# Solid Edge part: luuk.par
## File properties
Author: Mac
Template: Normal.par
Last saved by: Mac
Revision: 4
Application: Solid Edge
Density: 1300,000 kg/m^3
Accuracy: 0,990
Material: Epoxy, cast rigid
Face Style: White
Fill Style: ANSI34(Plastic)
Virtual Style: Shiny resin yellow
Coef. of Thermal Exp: 5.9e-05
Thermal Conductivity: 2.1
Specific Heat: 0.0
Modulus of Elasticity: 3102640650.0
Poission's Ratio: 0.37
Yield Stress: 65500191.5
Ultimate Stress: 0.0
Elongation: 0.0
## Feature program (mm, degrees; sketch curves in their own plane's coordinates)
sketch for "unnamed Protrusion 1" plane through (0, 0, 0) normal (0, 0, 1) x-axis (1, 0, 0)
  line (-16, 26) -> (0, 26)
  line (0, 26) -> (0, 0)
  line (0, 0) -> (-16, 0)
  line (-16, 0) -> (-16, 26)
extrude "unnamed Protrusion 1" add finite 0.5 along +normal
fillet "Round_1" radius 0.02
thinwall "Thinwall_2"  Thickness = 0.1 mm
sketch for "unnamed Cutout 1" plane through (-8, 13, 0.5) normal (0, 0, 1) x-axis (1, 0, 0)
  circle centre (-6.43, 0) radius 0.7
extrude "unnamed Cutout 1" cut through along -normal
sketch for "ExtrudedCutout_2" #1 plane through (-8, 13, 0.5) normal (0, 0, 1) x-axis (1, 0, 0)
  line (7.85, 9.4) -> (7.1461, 9.5241)
  arc centre (7.16, 9.6029) radius 0.08 from (7.08, 9.6029) to (7.1461, 9.5241) ccw
  line (7.08, 9.6029) -> (7.08, 10.3971)
  arc centre (7.16, 10.3971) radius 0.08 from (7.08, 10.3971) to (7.1461, 10.4759) cw
  line (7.85, 10.6) -> (7.1461, 10.4759)
  line (7.85, 10.6) -> (8.2871, 10.6)
  line (8.2871, 9.4) -> (8.2871, 10.6)
  line (7.85, 9.4) -> (8.2871, 9.4)
sketch for "ExtrudedCutout_2" #2 plane through (-8, 13, 0.5) normal (0, 0, 1) x-axis (1, 0, 0)
  line (7.85, -9.4) -> (7.1461, -9.5241)
  arc centre (7.16, -9.6029) radius 0.08 from (7.08, -9.6029) to (7.1461, -9.5241) cw
  line (7.08, -9.6029) -> (7.08, -10.3971)
  arc centre (7.16, -10.3971) radius 0.08 from (7.08, -10.3971) to (7.1461, -10.4759) ccw
  line (7.85, -10.6) -> (7.1461, -10.4759)
  line (7.85, -10.6) -> (8.2871, -10.6)
  line (8.2871, -9.4) -> (8.2871, -10.6)
  line (7.85, -9.4) -> (8.2871, -9.4)
sketch for "ExtrudedCutout_2" #3 plane through (-8, 13, 0.5) normal (0, 0, 1) x-axis (1, 0, 0)
  line (7.85, 0.6) -> (7.1461, 0.4759)
  arc centre (7.16, 0.3971) radius 0.08 from (7.08, 0.3971) to (7.1461, 0.4759) cw
  line (7.08, 0.3971) -> (7.08, -0.3971)
  arc centre (7.16, -0.3971) radius 0.08 from (7.08, -0.3971) to (7.1461, -0.4759) ccw
  line (7.85, -0.6) -> (7.1461, -0.4759)
  line (7.85, -0.6) -> (8.2871, -0.6)
  line (8.2871, 0.6) -> (8.2871, -0.6)
  line (7.85, 0.6) -> (8.2871, 0.6)
extrude "ExtrudedCutout_2" cut finite 0.01 along -normal
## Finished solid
Body 1: solid body, 48 faces, 122 edges, 76 vertices.
  Faces by surface: plane 29, cylinder 15, sphere 4
  Edges by curve: line 86, circle 36
Bounding box of the edges (mm; curved faces can reach further): 16.000 x 26.000 x 0.500, from (-16, 0, 0) to (0, 26, 0.5).
Cylindrical faces by radius (mm): R0.02 x8, R0.08 x6, R0.7 x1
Spherical faces by radius (mm): R0.02 x4
Planar faces by outward normal: +x 5, +y 5, +z 4, -x 2, -y 5, -z 2, oblique 6
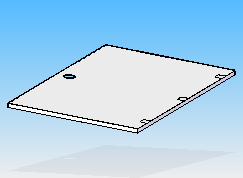
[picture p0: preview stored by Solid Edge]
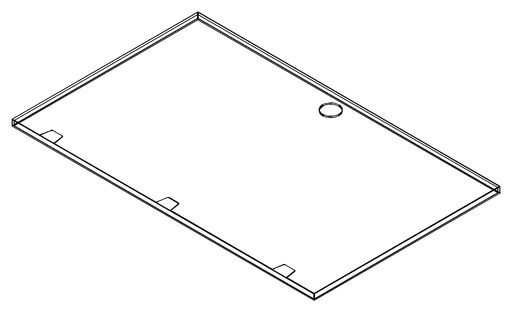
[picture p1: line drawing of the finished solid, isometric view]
